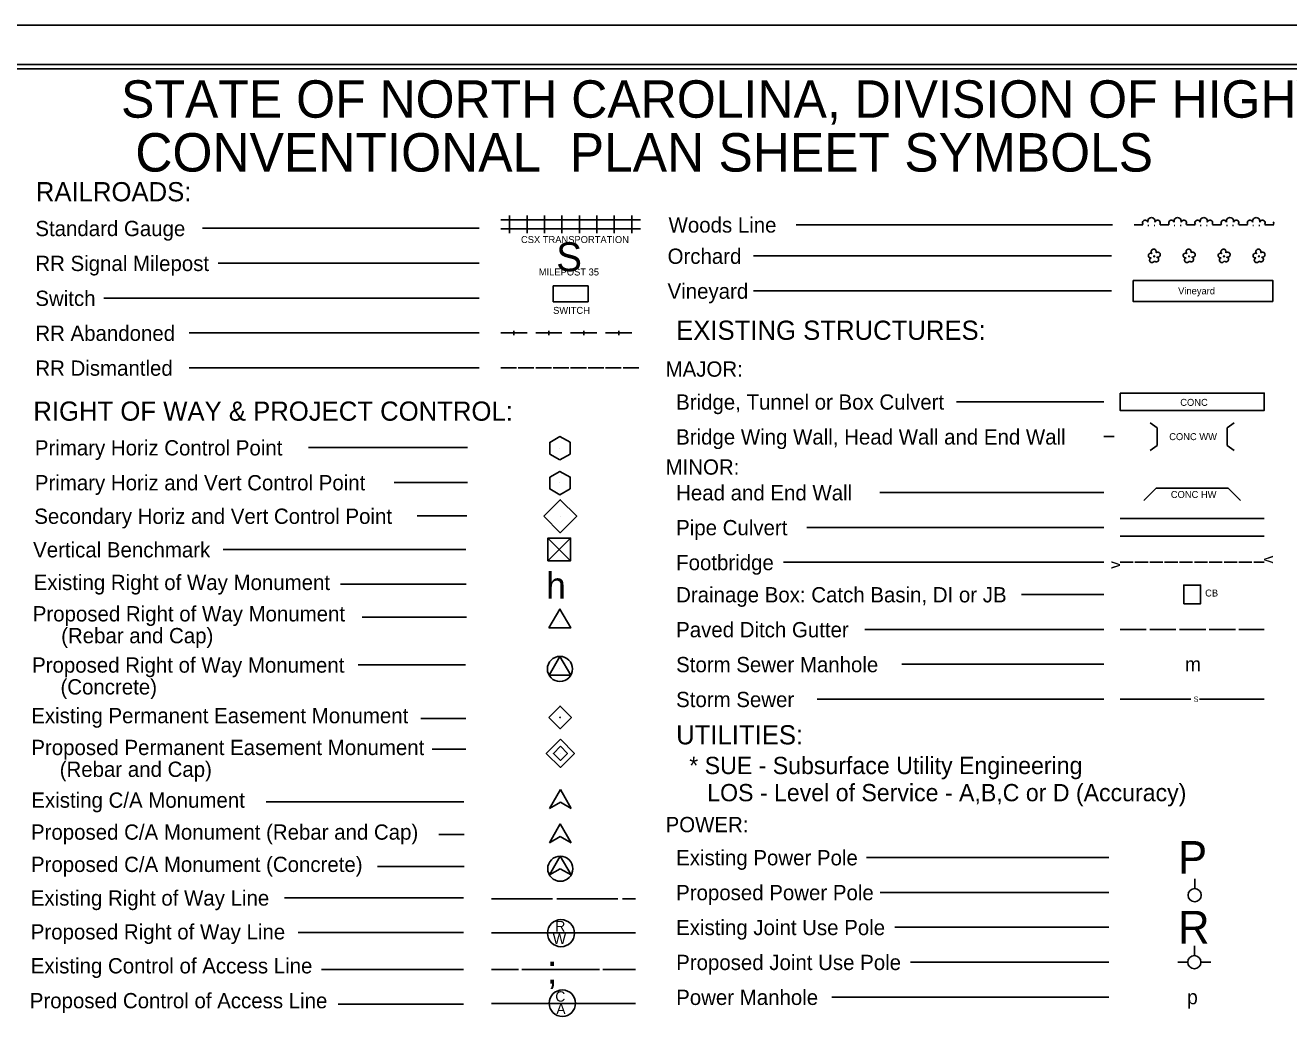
# Model space of a CAD drawing. Extents: x 2163579 to 2286010, y 210234 to 425257.
# Drawn here: x 2203342 to 2239520, y 236773 to 265234 of the extents above; entities that cross this region are included whole.
import ezdxf

# ---------------------------------------------------------------- set-up
doc = ezdxf.new("R2010")
doc.units = 0
for name, color, linetype in [('Default', 7, 'Continuous'), ('Prop ROW Permanent Easement CELL', 7, 'Continuous'), ('Sheet Cutting Line CELL', 7, 'Continuous'), ('Sheet Plot Border Inside CELL', 7, 'Continuous'), ('Sheet Plot Border Outside CELL', 7, 'Continuous'), ('Sheet Symbology CELL', 7, 'Continuous')]:
    doc.layers.add(name, color=color, linetype=linetype)

msp = doc.modelspace()

# ---------------------------------------------------------------- linework, layer by layer
at = {"layer": 'Default'}
for p, q in [((2218651, 253119), (2218651, 253119)), ((2218651, 252121), (2218651, 252121)), ((2218657, 251167), (2218657, 251167)), ((2218632, 250217), (2218632, 250217)), ((2218656, 245406), (2218656, 245406))]:
    msp.add_line(p, q, dxfattribs=at)
for points in [[(2218651, 252787), (2218361, 252951), (2218361, 253284), (2218651, 253452), (2218941, 253287), (2218941, 252951), (2218651, 252787)], [(2218956, 250541), (2218308, 249892), (2218632, 250217), (2218956, 249892), (2218308, 250541)], [(2218632, 250217), (2218956, 250541), (2218308, 250541), (2218632, 250217)], [(2218632, 250217), (2218308, 249892), (2218956, 249892), (2218632, 250217)]]:
    msp.add_lwpolyline(points, dxfattribs=at)
for points in [[(2218359, 252290), (2218652, 252453), (2218946, 252292), (2218941, 251956), (2218648, 251786), (2218359, 251949)], [(2218187, 251169), (2218660, 251642), (2219134, 251168), (2218661, 250695)], [(2218308, 250541), (2218956, 250541), (2218956, 249892), (2218308, 249892)], [(2218331, 245406), (2218656, 245731), (2218980, 245406), (2218656, 245081)]]:
    msp.add_lwpolyline(points, close=True, dxfattribs=at)
msp.add_circle((2218656, 245406), 6.32, dxfattribs=at)
at = {"layer": 'Prop ROW Permanent Easement CELL'}
msp.add_line((2218665, 244376), (2218665, 244376), dxfattribs=at)
for points in [[(2218665, 244778), (2219067, 244376), (2218665, 243973), (2218262, 244376)], [(2218665, 244577), (2218866, 244376), (2218665, 244175), (2218463, 244376)]]:
    msp.add_lwpolyline(points, close=True, dxfattribs=at)
at = {"layer": 'Sheet Cutting Line CELL'}
msp.add_line((2259408, 265234), (2175208, 265234), dxfattribs=at)
at = {"layer": 'Sheet Plot Border Inside CELL'}
msp.add_lwpolyline([(2175858, 211357), (2259183, 211357), (2259183, 264112), (2175858, 264112)], close=True, dxfattribs=at)
at = {"layer": 'Sheet Plot Border Outside CELL'}
msp.add_lwpolyline([(2175208, 210234), (2259408, 210234), (2259408, 265234), (2175208, 265234)], close=True, dxfattribs=at)
at = {"layer": 'Sheet Symbology CELL'}
for p, q in [((2217209, 259282), (2217209, 259782)), ((2217709, 259282), (2217709, 259782)), ((2218209, 259282), (2218209, 259782)), ((2218709, 259282), (2218709, 259782)), ((2219209, 259282), (2219209, 259782)), ((2219709, 259282), (2219709, 259782)), ((2220209, 259282), (2220209, 259782)), ((2220709, 259282), (2220709, 259782)), ((2216339, 259419), (2208418, 259419)), ((2216959, 259657), (2217459, 259657)), ((2216959, 259407), (2217459, 259407)), ((2217459, 259657), (2217959, 259657)), ((2217459, 259407), (2217959, 259407)), ((2217959, 259657), (2218459, 259657)), ((2217959, 259407), (2218459, 259407)), ((2218459, 259657), (2218959, 259657)), ((2218459, 259407), (2218959, 259407)), ((2218959, 259657), (2219459, 259657)), ((2218959, 259407), (2219459, 259407)), ((2219459, 259657), (2219959, 259657)), ((2219459, 259407), (2219959, 259407)), ((2219959, 259657), (2220459, 259657)), ((2219959, 259407), (2220459, 259407)), ((2220459, 259657), (2220959, 259657)), ((2220459, 259407), (2220959, 259407)), ((2234471, 259521), (2225415, 259521)), ((2235090, 259521), (2235340, 259521)), ((2235488, 259496), (2235513, 259496)), ((2235663, 259496), (2235688, 259496)), ((2235840, 259521), (2236090, 259521)), ((2236238, 259496), (2236263, 259496)), ((2236413, 259496), (2236438, 259496)), ((2236590, 259521), (2236840, 259521)), ((2236988, 259496), (2237013, 259496)), ((2237163, 259496), (2237188, 259496)), ((2237340, 259521), (2237590, 259521)), ((2237738, 259496), (2237763, 259496)), ((2237913, 259496), (2237938, 259496)), ((2238090, 259521), (2238340, 259521)), ((2238488, 259496), (2238513, 259496)), ((2238663, 259496), (2238688, 259496)), ((2238840, 259521), (2239090, 259521)), ((2216339, 258419), (2208862, 258419)), ((2234442, 258625), (2224196, 258625)), ((2234442, 257625), (2224196, 257625)), ((2216339, 257419), (2205593, 257419)), ((2216339, 256419), (2208031, 256419)), ((2216959, 256419), (2217709, 256419)), ((2217334, 256481), (2217334, 256356)), ((2217959, 256419), (2218709, 256419)), ((2218334, 256481), (2218334, 256356)), ((2218959, 256419), (2219709, 256419)), ((2219334, 256481), (2219334, 256356)), ((2219959, 256419), (2220709, 256419)), ((2220334, 256481), (2220334, 256356)), ((2216339, 255419), (2208031, 255419)), ((2216339, 255419), (2208031, 255419)), ((2216959, 255419), (2217409, 255419)), ((2217459, 255419), (2217909, 255419)), ((2217959, 255419), (2218409, 255419)), ((2218459, 255419), (2218909, 255419)), ((2218959, 255419), (2219409, 255419)), ((2219459, 255419), (2219909, 255419)), ((2219959, 255419), (2220409, 255419)), ((2220459, 255419), (2220909, 255419)), ((2234227, 254449), (2230005, 254449)), ((2235549, 253843), (2235754, 253699)), ((2235754, 253699), (2235754, 253199)), ((2237959, 253843), (2237754, 253699)), ((2237754, 253699), (2237754, 253199)), ((2234227, 253449), (2234526, 253449)), ((2216005, 253138), (2211453, 253138)), ((2235549, 253056), (2235754, 253199)), ((2237959, 253056), (2237754, 253199)), ((2216005, 252138), (2213909, 252138)), ((2234227, 251850), (2227812, 251850)), ((2235369, 251621), (2235723, 251975)), ((2235723, 251975), (2237785, 251975)), ((2237785, 251975), (2238139, 251621)), ((2215989, 251178), (2214561, 251178)), ((2234692, 251100), (2238817, 251100)), ((2234227, 250850), (2225717, 250850)), ((2234692, 250600), (2238817, 250600)), ((2215954, 250217), (2209012, 250217)), ((2234227, 249850), (2225053, 249850)), ((2234692, 249850), (2235067, 249850)), ((2235117, 249850), (2235492, 249850)), ((2235542, 249850), (2235917, 249850)), ((2235967, 249850), (2236342, 249850)), ((2236392, 249850), (2236767, 249850)), ((2236817, 249850), (2237192, 249850)), ((2237242, 249850), (2237617, 249850)), ((2237667, 249850), (2238042, 249850)), ((2238092, 249850), (2238467, 249850)), ((2238517, 249850), (2238817, 249850)), ((2215970, 249218), (2212367, 249218)), ((2234227, 248928), (2231867, 248928)), ((2215975, 248278), (2212988, 248278)), ((2218651, 248148), (2218651, 248148)), ((2234227, 247928), (2227379, 247928)), ((2234692, 247928), (2235442, 247928)), ((2235542, 247928), (2236292, 247928)), ((2236392, 247928), (2237142, 247928)), ((2237242, 247928), (2237992, 247928)), ((2238092, 247928), (2238817, 247928)), ((2215950, 246908), (2212876, 246908)), ((2218652, 246794), (2218652, 246794)), ((2234227, 246928), (2228443, 246928)), ((2234227, 245928), (2226017, 245928)), ((2234692, 245928), (2236718, 245928)), ((2236968, 245928), (2238817, 245928)), ((2215954, 245373), (2214664, 245373)), ((2215954, 244492), (2214990, 244492)), ((2218351, 242797), (2218664, 243337)), ((2218664, 243337), (2218976, 242797)), ((2215904, 242982), (2210242, 242982)), ((2218664, 242977), (2218351, 242797)), ((2218976, 242797), (2218664, 242977)), ((2215909, 242055), (2215181, 242055)), ((2218349, 241816), (2218662, 242356)), ((2218662, 242356), (2218974, 241816)), ((2218662, 241996), (2218349, 241816)), ((2218974, 241816), (2218662, 241996)), ((2218349, 240891), (2218662, 241431)), ((2218662, 241431), (2218974, 240891)), ((2234366, 241394), (2227431, 241394)), ((2215909, 241130), (2213426, 241130)), ((2218662, 241071), (2218349, 240891)), ((2218974, 240891), (2218662, 241071)), ((2236827, 240499), (2236827, 240781)), ((2215887, 240241), (2210761, 240241)), ((2234366, 240394), (2227820, 240394)), ((2216689, 240212), (2218439, 240212)), ((2218564, 240212), (2220314, 240212)), ((2220439, 240212), (2220814, 240212)), ((2215887, 239241), (2211161, 239241)), ((2216689, 239234), (2220814, 239234)), ((2234366, 239394), (2228240, 239394)), ((2236817, 238582), (2236817, 238863)), ((2215887, 238184), (2211821, 238184)), ((2216689, 238184), (2217462, 238184)), ((2217562, 238184), (2219782, 238184)), ((2219882, 238184), (2220814, 238184)), ((2234366, 238394), (2228690, 238394)), ((2236629, 238394), (2236348, 238394)), ((2237004, 238394), (2237285, 238394)), ((2234366, 237394), (2226441, 237394)), ((2215887, 237193), (2212305, 237193)), ((2216689, 237212), (2220814, 237212))]:
    msp.add_line(p, q, dxfattribs=at)
for points in [[(2258558, 263984), (2183558, 263984), (2183558, 211535), (2258558, 211535)], [(2218459, 257767), (2219459, 257767), (2219459, 257312), (2218459, 257312)], [(2236514, 248662), (2236994, 248662), (2236994, 249194), (2236514, 249194)], [(2218338, 247968), (2218651, 248508), (2218963, 247968)], [(2218339, 246614), (2218652, 247154), (2218964, 246614)]]:
    msp.add_lwpolyline(points, close=True, dxfattribs=at)
for points in [[(2235715, 258712), (2235722, 258727), (2235725, 258742), (2235722, 258757), (2235720, 258772), (2235712, 258785), (2235705, 258797), (2235692, 258807), (2235680, 258815), (2235662, 258820), (2235650, 258820), (2235635, 258817), (2235620, 258812), (2235607, 258805), (2235595, 258795), (2235587, 258780), (2235582, 258767), (2235580, 258752), (2235580, 258737), (2235582, 258722), (2235590, 258710), (2235600, 258695), (2235587, 258702), (2235572, 258705), (2235557, 258705), (2235545, 258700), (2235532, 258695), (2235520, 258685), (2235510, 258675), (2235502, 258662), (2235500, 258650), (2235497, 258632), (2235500, 258620), (2235505, 258607), (2235515, 258595), (2235522, 258585), (2235535, 258577), (2235550, 258570), (2235562, 258567), (2235577, 258567), (2235565, 258562), (2235552, 258552), (2235545, 258542), (2235540, 258527), (2235535, 258512), (2235535, 258500), (2235537, 258485), (2235545, 258472), (2235552, 258460), (2235562, 258450), (2235575, 258442), (2235587, 258437), (2235602, 258437), (2235617, 258437), (2235630, 258440), (2235642, 258450), (2235655, 258457), (2235667, 258480)], [(2235667, 258480), (2235697, 258462), (2235712, 258457), (2235727, 258455), (2235742, 258457), (2235755, 258462), (2235767, 258470), (2235780, 258480), (2235787, 258492), (2235792, 258505), (2235797, 258520), (2235795, 258535), (2235792, 258550), (2235782, 258565), (2235775, 258575), (2235762, 258582), (2235747, 258590), (2235762, 258587), (2235780, 258587), (2235792, 258592), (2235807, 258600), (2235820, 258607), (2235830, 258620), (2235837, 258635), (2235840, 258650), (2235842, 258665), (2235840, 258680), (2235835, 258695), (2235825, 258707), (2235812, 258720), (2235800, 258727), (2235785, 258732), (2235770, 258735), (2235755, 258735), (2235740, 258730), (2235727, 258722), (2235715, 258712)], [(2236715, 258712), (2236722, 258727), (2236725, 258742), (2236722, 258757), (2236720, 258772), (2236712, 258785), (2236705, 258797), (2236692, 258807), (2236680, 258815), (2236662, 258820), (2236650, 258820), (2236635, 258817), (2236620, 258812), (2236607, 258805), (2236595, 258795), (2236587, 258780), (2236582, 258767), (2236580, 258752), (2236580, 258737), (2236582, 258722), (2236590, 258710), (2236600, 258695), (2236587, 258702), (2236572, 258705), (2236557, 258705), (2236545, 258700), (2236532, 258695), (2236520, 258685), (2236510, 258675), (2236502, 258662), (2236500, 258650), (2236497, 258632), (2236500, 258620), (2236505, 258607), (2236515, 258595), (2236522, 258585), (2236535, 258577), (2236550, 258570), (2236562, 258567), (2236577, 258567), (2236565, 258562), (2236552, 258552), (2236545, 258542), (2236540, 258527), (2236535, 258512), (2236535, 258500), (2236537, 258485), (2236545, 258472), (2236552, 258460), (2236562, 258450), (2236575, 258442), (2236587, 258437), (2236602, 258437), (2236617, 258437), (2236630, 258440), (2236642, 258450), (2236655, 258457), (2236667, 258480)], [(2236667, 258480), (2236697, 258462), (2236712, 258457), (2236727, 258455), (2236742, 258457), (2236755, 258462), (2236767, 258470), (2236780, 258480), (2236787, 258492), (2236792, 258505), (2236797, 258520), (2236795, 258535), (2236792, 258550), (2236782, 258565), (2236775, 258575), (2236762, 258582), (2236747, 258590), (2236762, 258587), (2236780, 258587), (2236792, 258592), (2236807, 258600), (2236820, 258607), (2236830, 258620), (2236837, 258635), (2236840, 258650), (2236842, 258665), (2236840, 258680), (2236835, 258695), (2236825, 258707), (2236812, 258720), (2236800, 258727), (2236785, 258732), (2236770, 258735), (2236755, 258735), (2236740, 258730), (2236727, 258722), (2236715, 258712)], [(2237715, 258712), (2237722, 258727), (2237725, 258742), (2237722, 258757), (2237720, 258772), (2237712, 258785), (2237705, 258797), (2237692, 258807), (2237680, 258815), (2237662, 258820), (2237650, 258820), (2237635, 258817), (2237620, 258812), (2237607, 258805), (2237595, 258795), (2237587, 258780), (2237582, 258767), (2237580, 258752), (2237580, 258737), (2237582, 258722), (2237590, 258710), (2237600, 258695), (2237587, 258702), (2237572, 258705), (2237557, 258705), (2237545, 258700), (2237532, 258695), (2237520, 258685), (2237510, 258675), (2237502, 258662), (2237500, 258650), (2237497, 258632), (2237500, 258620), (2237505, 258607), (2237515, 258595), (2237522, 258585), (2237535, 258577), (2237550, 258570), (2237562, 258567), (2237577, 258567), (2237565, 258562), (2237552, 258552), (2237545, 258542), (2237540, 258527), (2237535, 258512), (2237535, 258500), (2237537, 258485), (2237545, 258472), (2237552, 258460), (2237562, 258450), (2237575, 258442), (2237587, 258437), (2237602, 258437), (2237617, 258437), (2237630, 258440), (2237642, 258450), (2237655, 258457), (2237667, 258480)], [(2237667, 258480), (2237697, 258462), (2237712, 258457), (2237727, 258455), (2237742, 258457), (2237755, 258462), (2237767, 258470), (2237780, 258480), (2237787, 258492), (2237792, 258505), (2237797, 258520), (2237795, 258535), (2237792, 258550), (2237782, 258565), (2237775, 258575), (2237762, 258582), (2237747, 258590), (2237762, 258587), (2237780, 258587), (2237792, 258592), (2237807, 258600), (2237820, 258607), (2237830, 258620), (2237837, 258635), (2237840, 258650), (2237842, 258665), (2237840, 258680), (2237835, 258695), (2237825, 258707), (2237812, 258720), (2237800, 258727), (2237785, 258732), (2237770, 258735), (2237755, 258735), (2237740, 258730), (2237727, 258722), (2237715, 258712)], [(2238715, 258712), (2238722, 258727), (2238725, 258742), (2238722, 258757), (2238720, 258772), (2238712, 258785), (2238705, 258797), (2238692, 258807), (2238680, 258815), (2238662, 258820), (2238650, 258820), (2238635, 258817), (2238620, 258812), (2238607, 258805), (2238595, 258795), (2238587, 258780), (2238582, 258767), (2238580, 258752), (2238580, 258737), (2238582, 258722), (2238590, 258710), (2238600, 258695), (2238587, 258702), (2238572, 258705), (2238557, 258705), (2238545, 258700), (2238532, 258695), (2238520, 258685), (2238510, 258675), (2238502, 258662), (2238500, 258650), (2238497, 258632), (2238500, 258620), (2238505, 258607), (2238515, 258595), (2238522, 258585), (2238535, 258577), (2238550, 258570), (2238562, 258567), (2238577, 258567), (2238565, 258562), (2238552, 258552), (2238545, 258542), (2238540, 258527), (2238535, 258512), (2238535, 258500), (2238537, 258485), (2238545, 258472), (2238552, 258460), (2238562, 258450), (2238575, 258442), (2238587, 258437), (2238602, 258437), (2238617, 258437), (2238630, 258440), (2238642, 258450), (2238655, 258457), (2238667, 258480)], [(2238667, 258480), (2238697, 258462), (2238712, 258457), (2238727, 258455), (2238742, 258457), (2238755, 258462), (2238767, 258470), (2238780, 258480), (2238787, 258492), (2238792, 258505), (2238797, 258520), (2238795, 258535), (2238792, 258550), (2238782, 258565), (2238775, 258575), (2238762, 258582), (2238747, 258590), (2238762, 258587), (2238780, 258587), (2238792, 258592), (2238807, 258600), (2238820, 258607), (2238830, 258620), (2238837, 258635), (2238840, 258650), (2238842, 258665), (2238840, 258680), (2238835, 258695), (2238825, 258707), (2238812, 258720), (2238800, 258727), (2238785, 258732), (2238770, 258735), (2238755, 258735), (2238740, 258730), (2238727, 258722), (2238715, 258712)], [(2235672, 258625), (2235665, 258625), (2235660, 258622), (2235655, 258620), (2235655, 258612), (2235655, 258607), (2235660, 258602), (2235667, 258602), (2235672, 258602), (2235677, 258607), (2235680, 258615), (2235677, 258620), (2235672, 258625)], [(2236672, 258625), (2236665, 258625), (2236660, 258622), (2236655, 258620), (2236655, 258612), (2236655, 258607), (2236660, 258602), (2236667, 258602), (2236672, 258602), (2236677, 258607), (2236680, 258615), (2236677, 258620), (2236672, 258625)], [(2237672, 258625), (2237665, 258625), (2237660, 258622), (2237655, 258620), (2237655, 258612), (2237655, 258607), (2237660, 258602), (2237667, 258602), (2237672, 258602), (2237677, 258607), (2237680, 258615), (2237677, 258620), (2237672, 258625)], [(2238672, 258625), (2238665, 258625), (2238660, 258622), (2238655, 258620), (2238655, 258612), (2238655, 258607), (2238660, 258602), (2238667, 258602), (2238672, 258602), (2238677, 258607), (2238680, 258615), (2238677, 258620), (2238672, 258625)], [(2235062, 257925), (2239062, 257925), (2239062, 257325), (2235062, 257325), (2235062, 257925)], [(2234692, 254699), (2238817, 254699), (2238817, 254199), (2234692, 254199), (2234692, 254699)]]:
    msp.add_lwpolyline(points, dxfattribs=at)
for centre, radius in [((2218652, 246794), 360), ((2218662, 241071), 360), ((2236827, 240312), 188), ((2218681, 239224), 388), ((2236817, 238394), 188), ((2218721, 237218), 379)]:
    msp.add_circle(centre, radius, dxfattribs=at)
for centre, radius, start, end in [((2235413, 259572), 79.1, 18.435, 219.2315), ((2235588, 259622), 103, 345.9638, 194.0362), ((2235763, 259572), 79.1, 320.7685, 161.5651), ((2236163, 259572), 79.1, 18.435, 219.2315), ((2236338, 259622), 103, 345.9638, 194.0362), ((2236513, 259572), 79.1, 320.7685, 161.5651), ((2236913, 259572), 79.1, 18.435, 219.2315), ((2237088, 259622), 103, 345.9638, 194.0362), ((2237263, 259572), 79.1, 320.7685, 161.5651), ((2237663, 259572), 79.1, 18.435, 219.2315), ((2237838, 259622), 103, 345.9638, 194.0362), ((2238013, 259572), 79.1, 320.7685, 161.5651), ((2238413, 259572), 79.1, 18.435, 219.2315), ((2238588, 259622), 103, 345.9638, 194.0362), ((2238763, 259572), 79.1, 320.7685, 161.5651), ((2239163, 259572), 79.1, 156.251, 203.749)]:
    msp.add_arc(centre, radius, start, end, dxfattribs=at)

# ---------------------------------------------------------------- texts
for s, height, p in [('STATE OF NORTH CAROLINA, DIVISION OF HIGHWAYS', 1070.95, (2206086, 262586)), ('CONVENTIONAL  PLAN SHEET SYMBOLS', 1101.61, (2206492, 261042)), ('RAILROADS:', 550, (2203645, 260191)), ('Woods Line', 437.5, (2221763, 259295)), ('Standard Gauge', 437.5, (2203631, 259193)), ('S', 825, (2218547, 258188)), ('Orchard', 437.5, (2221734, 258399)), ('RR Signal Milepost', 437.5, (2203631, 258193)), ('Switch', 437.5, (2203631, 257193)), ('Vineyard', 437.5, (2221734, 257399)), ('RR Abandoned', 437.5, (2203631, 256193)), ('EXISTING STRUCTURES:', 550, (2221979, 256222)), ('RR Dismantled', 437.5, (2203631, 255193)), ('MAJOR:', 437.5, (2221677, 255166)), ('RIGHT OF WAY & PROJECT CONTROL:', 550, (2203574, 253905)), ('Bridge, Tunnel or Box Culvert', 437.5, (2221979, 254222)), ('CONC', 200, (2236414, 254331)), ('Bridge Wing Wall, Head Wall and End Wall', 437.5, (2221979, 253222)), ('Primary Horiz Control Point', 437.5, (2203617, 252910)), ('MINOR:', 437.5, (2221677, 252360)), ('Primary Horiz and Vert Control Point', 437.5, (2203617, 251910)), ('Head and End Wall', 437.5, (2221979, 251622)), ('Secondary Horiz and Vert Control Point', 437.5, (2203601, 250950)), ('Pipe Culvert', 437.5, (2221979, 250623)), ('Vertical Benchmark', 437.5, (2203567, 249989)), ('Footbridge', 437.5, (2221979, 249623)), ('Existing Right of Way Monument', 437.5, (2203583, 249054)), ('h', 750, (2218262, 248809)), ('Drainage Box: Catch Basin, DI or JB', 437.5, (2221979, 248701)), ('Proposed Right of Way Monument', 437.5, (2203557, 248155)), ('     (Rebar and Cap)', 437.5, (2203557, 247530)), ('Paved Ditch Gutter', 437.5, (2221979, 247700)), ('Proposed Right of Way Monument', 437.5, (2203538, 246687)), ('Storm Sewer Manhole', 437.5, (2221979, 246700)), ('m', 412, (2236548, 246722)), ('     (Concrete)', 437.5, (2203538, 246062)), ('Storm Sewer', 437.5, (2221979, 245700)), ('Existing Permanent Easement Monument', 437.5, (2203514, 245238)), ('S', 150, (2236798, 245853)), ('UTILITIES:', 550, (2221979, 244632)), ('Proposed Permanent Easement Monument', 437.5, (2203516, 244326)), ('     (Rebar and Cap)', 437.5, (2203516, 243701)), ('Existing C/A Monument', 437.5, (2203517, 242817)), ('POWER:', 437.5, (2221677, 242117)), ('Proposed C/A Monument (Rebar and Cap)', 437.5, (2203506, 241902)), ('P', 938, (2236348, 240925)), ('Proposed C/A Monument (Concrete)', 437.5, (2203506, 240977)), ('Existing Power Pole', 437.5, (2221979, 241167)), ('Proposed Power Pole', 437.5, (2221979, 240167)), ('Existing Right of Way Line', 437.5, (2203500, 240013)), ('R', 938, (2236348, 238925)), ('Proposed Right of Way Line', 437.5, (2203500, 239044)), ('R', 304, (2218514, 239270)), ('Existing Joint Use Pole', 437.5, (2221979, 239168)), ('W', 304, (2218445, 238912)), ('Existing Control of Access Line', 437.5, (2203500, 238071)), ('Proposed Joint Use Pole', 437.5, (2221980, 238167)), (';', 825, (2218278, 237775)), ('Proposed Control of Access Line', 437.5, (2203472, 237072)), ('C', 297, (2218520, 237262)), ('Power Manhole', 437.5, (2221980, 237167)), ('p', 412, (2236610, 237188)), ('A', 297, (2218549, 236906))]:
    msp.add_text(s, height=height, dxfattribs=at).set_placement(p)
for s, height, rotation, p in [('CSX TRANSPORTATION', 200, 360, (2217537, 258995)), ('MILEPOST 35', 200, 360, (2218046, 258066)), ('Vineyard', 200, 0, (2236353, 257525)), ('SWITCH', 200, 360, (2218456, 256966)), ('CONC WW', 200, 0, (2236098, 253349)), ('CONC HW', 200, 360, (2236144, 251692)), ('v', 330, 270.2409, (2238816, 250037)), ('v', 330, 89.7591, (2234691, 249663)), ('CB', 200, 360, (2237126, 248869)), ('* SUE - Subsurface Utility Engineering', 495, 360, (2222355, 243781)), ('LOS - Level of Service - A,B,C or D (Accuracy) ', 495, 360, (2222869, 243003))]:
    msp.add_text(s, height=height, rotation=rotation, dxfattribs=at).set_placement(p)

doc.saveas('drawing.dxf')
